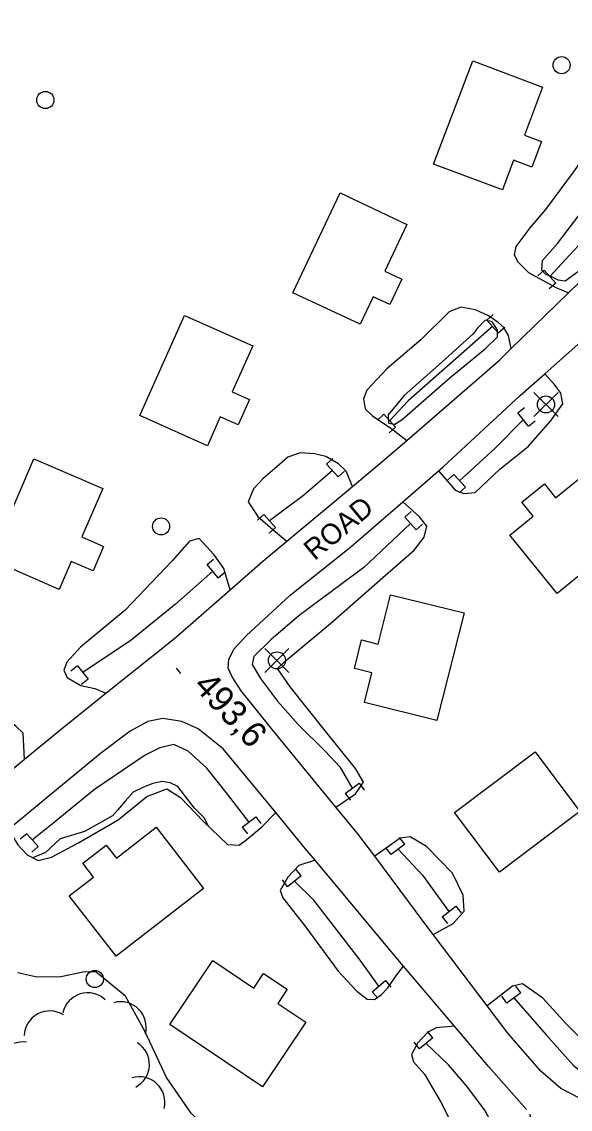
# Model space of a CAD drawing. Extents: x 642515 to 647219, y 6080136 to 6084356.
# Drawn here: x 643716 to 643780.2, y 6081485.1 to 6081612.4 of the extents above; entities that cross this region are included whole.
import ezdxf

# ---------------------------------------------------------------- set-up
doc = ezdxf.new("R2010")
doc.units = 0
for name, color, linetype in [('Level 19', 7, 'Continuous'), ('Level 2', 7, 'Continuous'), ('Level 21', 7, 'Continuous'), ('Level 26', 7, 'Continuous'), ('Level 3', 7, 'Continuous'), ('Level 31', 7, 'Continuous'), ('Level 36', 7, 'Continuous'), ('Level 4', 7, 'Continuous'), ('Level 44', 7, 'Continuous')]:
    doc.layers.add(name, color=color, linetype=linetype)

msp = doc.modelspace()

# ---------------------------------------------------------------- linework, layer by layer
at = {"layer": 'Level 19'}
for points in [[(643799.39, 6081615.12), (643798.24, 6081616.05), (643796.81, 6081616.85), (643795.49, 6081617.32), (643793.8, 6081617.29), (643792.68, 6081616.45), (643791.81, 6081614.33), (643789.04, 6081609.27), (643786.74, 6081604.39), (643783.98, 6081599.77), (643780.67, 6081594.95), (643777.33, 6081590.45), (643775.5, 6081588.27), (643773.83, 6081586.1), (643773.65, 6081585.12), (643774.07, 6081584.3), (643775.32, 6081583.05), (643777.33, 6081581.97), (643778.54, 6081581.29), (643780.02, 6081580.68)], [(643773.31, 6081574.14), (643773, 6081575.69), (643772.46, 6081576.62), (643771.77, 6081577.22), (643770.63, 6081578), (643769.13, 6081578.7), (643767.42, 6081578.99), (643766.05, 6081578.46), (643762.72, 6081575.17), (643758.75, 6081571.76), (643756.41, 6081569.27), (643756, 6081568.27), (643756.19, 6081567.11), (643757.06, 6081566.28), (643759.33, 6081564.74), (643761.09, 6081563.4)], [(643764.79, 6081559.83), (643766.75, 6081557.58), (643767.74, 6081557.17), (643769.07, 6081557.29), (643771.99, 6081560.03), (643775.28, 6081562.67), (643777.9, 6081565.66), (643779.35, 6081567.66), (643779.1, 6081568.93), (643778.39, 6081569.93), (643777.23, 6081571.2)], [(643754.73, 6081558), (643753.96, 6081559.81), (643753.06, 6081560.67), (643751.59, 6081561.5), (643750.28, 6081561.82), (643748.58, 6081561.95), (643747.16, 6081561.45), (643745.87, 6081560.32), (643744.27, 6081558.92), (643743.14, 6081557.72), (643742.51, 6081556.22), (643743.63, 6081554.48), (643745.69, 6081552.68), (643747.02, 6081551.59)], [(643752.77, 6081520.47), (643755.08, 6081522), (643756, 6081523.39), (643755.05, 6081524.98), (643751.4, 6081529.53), (643747.4, 6081534.55), (643745.93, 6081536.67), (643746.81, 6081537.49), (643752.19, 6081542), (643758.28, 6081547.33), (643761.94, 6081550.55), (643763.13, 6081552.08), (643763.41, 6081553.35), (643762.57, 6081554.46), (643760.6, 6081556.19)], [(643740.4, 6081545.91), (643739.63, 6081548.4), (643738.52, 6081549.98), (643736.74, 6081551.91), (643735.63, 6081551.6), (643733.61, 6081549.29), (643728.1, 6081543.52), (643722.87, 6081539.18), (643721.25, 6081537.42), (643720.91, 6081536.51), (643721.29, 6081535.65), (643722.88, 6081534.71), (643724.52, 6081534.33), (643725.84, 6081533.79)], [(643716.3, 6081526.08), (643716.15, 6081529.1), (643715.33, 6081529.89), (643714.31, 6081530.71), (643712.56, 6081530.87), (643709.93, 6081528.64), (643704.45, 6081523.24), (643701.69, 6081519.83), (643701.87, 6081519), (643703.2, 6081517.76), (643704.6, 6081516.72)], [(643714.44, 6081517.83), (643715.53, 6081516.05), (643716.61, 6081514.87), (643717.9, 6081514.19), (643719.45, 6081514.58), (643722.56, 6081516.23), (643727.29, 6081518.97), (643730.61, 6081521.72), (643732.97, 6081522.61), (643734.57, 6081521.58), (643737.21, 6081518.82), (643740.09, 6081516.07), (643741.46, 6081516), (643742.35, 6081516.66), (643744.1, 6081518.15), (643745.73, 6081519.81)], [(643764.18, 6081505.55), (643766.51, 6081506.83), (643767.78, 6081508.28), (643767.66, 6081510.13), (643766.44, 6081512.71), (643763.37, 6081515.85), (643761.49, 6081516.97), (643760.29, 6081516.81), (643757.32, 6081514.7)], [(643750.34, 6081514.23), (643748.44, 6081513.62), (643747.16, 6081512.25), (643746.26, 6081510.7), (643746.56, 6081509.83), (643749.24, 6081506.42), (643753.05, 6081501.27), (643755.22, 6081498.92), (643756.45, 6081497.99), (643757.3, 6081497.93), (643758.1, 6081498.51), (643758.86, 6081499.28), (643759.92, 6081500.84), (643760.68, 6081501.84)], [(643809.2, 6081503.18), (643808.48, 6081506.16), (643807.53, 6081507.83), (643805.66, 6081509.24), (643803.55, 6081509.5), (643801.32, 6081508.42), (643799.27, 6081506.59), (643796.08, 6081502.96), (643788.17, 6081496.5), (643784.22, 6081493.38), (643782.22, 6081492.64), (643779.84, 6081495.02), (643777.02, 6081498.1), (643774.62, 6081499.75), (643773.47, 6081499.48), (643770.5, 6081497.2)], [(643770.52, 6081451.44), (643769.08, 6081448.93), (643768.06, 6081449.67), (643766.12, 6081452.2), (643764.7, 6081454.88), (643763.07, 6081458.11), (643761.71, 6081459.84), (643759.61, 6081461.23), (643754.22, 6081464.21), (643750.58, 6081466.87), (643747.14, 6081470.1), (643742.9, 6081476.39), (643739.67, 6081480.88), (643735.84, 6081484.62), (643732.94, 6081488.82), (643730.41, 6081494.21), (643728.13, 6081498.32), (643724.68, 6081501.12), (643723.31, 6081501.19), (643720.41, 6081500.55), (643717.59, 6081500.6), (643715.5, 6081501.07)], [(643766.65, 6081494.81), (643764.52, 6081494.63), (643763.51, 6081494.08), (643762.38, 6081492.87), (643761.63, 6081491.49), (643761.85, 6081490.62), (643763.15, 6081489.18), (643765.06, 6081485.92), (643767.23, 6081481.67), (643768.34, 6081478.36), (643769.4, 6081476.9), (643770.71, 6081475.98), (643772.26, 6081475.76), (643773.42, 6081476.4), (643774.35, 6081477.55), (643775.71, 6081480.22), (643775.8, 6081482.49), (643775.52, 6081484.52)]]:
    msp.add_lwpolyline(points, dxfattribs=at)
at = {"layer": 'Level 2'}
for points in [[(643781.2, 6081583.17), (643779.63, 6081582.06), (643778.81, 6081582.17), (643777.98, 6081582.6), (643777.36, 6081582.84), (643776.88, 6081583.33), (643776.97, 6081584.46), (643778.72, 6081586.47), (643782.97, 6081592.02)], [(643768.86, 6081575.89), (643764.79, 6081572.19), (643760.78, 6081568.65), (643758.88, 6081566.39), (643758.94, 6081565.42), (643759.67, 6081565.31), (643760.53, 6081565.85), (643766.17, 6081570.75), (643770.27, 6081574.13), (643771.71, 6081575.52), (643771.69, 6081576.36), (643771.07, 6081577.29), (643770.25, 6081577.48), (643769.3, 6081576.49), (643768.86, 6081575.89)], [(643737.9, 6081518.16), (643737.33, 6081519.22), (643736.21, 6081520.35), (643734.27, 6081522.88), (643733.36, 6081523.3), (643732.42, 6081523.44), (643731.32, 6081523.21), (643730.22, 6081522.81), (643729.01, 6081522.21), (643728.08, 6081521.14), (643727.19, 6081520.12), (643726.59, 6081519.44), (643725.08, 6081518.57), (643723.34, 6081517.61), (643720.46, 6081516.74), (643718.77, 6081515.14), (643717.83, 6081514.76), (643717.25, 6081514.54)]]:
    msp.add_lwpolyline(points, dxfattribs=at)
at = {"layer": 'Level 21'}
for points in [[(643710.16, 6081521.04), (643716.3, 6081526.08), (643720.63, 6081529.63), (643725.84, 6081533.79), (643733.91, 6081540.23), (643740.4, 6081545.91), (643744.23, 6081549.26), (643747.02, 6081551.59), (643754.73, 6081558), (643758.17, 6081560.87), (643761.09, 6081563.4), (643771.97, 6081572.84), (643773.31, 6081574.14), (643780.02, 6081580.68), (643781.26, 6081581.89), (643784.65, 6081585.5), (643787.85, 6081590.11), (643792.99, 6081599.62), (643797.87, 6081611.24), (643799.39, 6081615.12)], [(643740.63, 6081535.72), (643740.16, 6081536.74), (643740.22, 6081537.75), (643740.82, 6081538.96), (643742.25, 6081540.5), (643747.42, 6081545.28), (643754.54, 6081550.92), (643760.6, 6081556.19), (643765.33, 6081560.3), (643774.37, 6081568.65), (643777.23, 6081571.2), (643781.14, 6081574.67)], [(643781.4, 6081486.36), (643779.1, 6081487.53), (643776.79, 6081489.56), (643772.91, 6081494.01), (643770.5, 6081497.2), (643764.18, 6081505.55), (643763.2, 6081506.83), (643757.32, 6081514.7), (643755.34, 6081517.35), (643752.77, 6081520.47), (643745.35, 6081529.5), (643741.66, 6081534.09), (643740.63, 6081535.72)], [(643775.08, 6081485.07), (643770.69, 6081490.05), (643766.65, 6081494.81), (643760.68, 6081501.84), (643760.42, 6081502.15), (643750.34, 6081514.23), (643749.18, 6081515.62), (643745.73, 6081519.81), (643739.58, 6081527.28), (643736.65, 6081529.63), (643734.74, 6081530.47), (643732.5, 6081530.84), (643730.75, 6081530.48), (643728.69, 6081529.34), (643725.19, 6081526.73), (643718.97, 6081521.6), (643714.44, 6081517.83)]]:
    msp.add_lwpolyline(points, dxfattribs=at)
at = {"layer": 'Level 26'}
for p, q in [((643777.18, 6081583.34), (643776.42, 6081582.68)), ((643777.18, 6081583.34), (643778.52, 6081581.82)), ((643778.52, 6081581.82), (643777.76, 6081581.16)), ((643770.45, 6081577.49), (643771.19, 6081578.15)), ((643771.79, 6081575.99), (643770.45, 6081577.49)), ((643771.79, 6081575.99), (643772.55, 6081576.65)), ((643758.4, 6081566.46), (643757.66, 6081565.78)), ((643758.4, 6081566.46), (643759.76, 6081564.96)), ((643774.09, 6081566.63), (643774.87, 6081567.25)), ((643775.35, 6081565.05), (643774.09, 6081566.63)), ((643775.35, 6081565.05), (643776.13, 6081565.67)), ((643759.76, 6081564.96), (643759.02, 6081564.3)), ((643751.68, 6081560.63), (643752.42, 6081561.29)), ((643753.02, 6081559.13), (643751.68, 6081560.63)), ((643753.02, 6081559.13), (643753.78, 6081559.79)), ((643766.6, 6081559.42), (643765.84, 6081558.76)), ((643766.6, 6081559.42), (643767.94, 6081557.92)), ((643767.94, 6081557.92), (643767.2, 6081557.26)), ((643760.83, 6081554.42), (643761.57, 6081555.08)), ((643744.35, 6081554.71), (643743.59, 6081554.05)), ((643744.35, 6081554.71), (643745.69, 6081553.21)), ((643762.19, 6081552.92), (643760.83, 6081554.42)), ((643762.19, 6081552.92), (643762.93, 6081553.6)), ((643745.69, 6081553.21), (643744.95, 6081552.55)), ((643737.69, 6081548.86), (643738.45, 6081549.5)), ((643738.99, 6081547.32), (643737.69, 6081548.86)), ((643738.99, 6081547.32), (643739.75, 6081547.96)), ((643722.51, 6081537.01), (643721.73, 6081536.37)), ((643722.51, 6081537.01), (643723.77, 6081535.43)), ((643723.77, 6081535.43), (643722.99, 6081534.81)), ((643753.87, 6081522.06), (643755.49, 6081523.26)), ((643755.49, 6081523.26), (643756.09, 6081522.46)), ((643753.87, 6081522.06), (643754.47, 6081521.26)), ((643741.8, 6081518.1), (643743.38, 6081519.34)), ((643743.38, 6081519.34), (643744, 6081518.56)), ((643741.8, 6081518.1), (643742.4, 6081517.32)), ((643716.56, 6081517.35), (643715.8, 6081516.69)), ((643716.56, 6081517.35), (643717.9, 6081515.85)), ((643760.84, 6081516.14), (643760.24, 6081516.92)), ((643717.9, 6081515.85), (643717.16, 6081515.19)), ((643759.26, 6081514.9), (643758.64, 6081515.68)), ((643760.84, 6081516.14), (643759.26, 6081514.9)), ((643748.7, 6081512.4), (643748.08, 6081513.18)), ((643747.12, 6081511.14), (643746.5, 6081511.94)), ((643748.7, 6081512.4), (643747.12, 6081511.14)), ((643765.22, 6081507.63), (643766.82, 6081508.87)), ((643766.82, 6081508.87), (643767.44, 6081508.09)), ((643765.22, 6081507.63), (643765.84, 6081506.85)), ((643757.04, 6081498.85), (643758.58, 6081500.15)), ((643758.58, 6081500.15), (643759.22, 6081499.39)), ((643757.04, 6081498.85), (643757.68, 6081498.09)), ((643774.42, 6081498.71), (643773.84, 6081499.51)), ((643772.8, 6081497.51), (643772.2, 6081498.31)), ((643774.42, 6081498.71), (643772.8, 6081497.51)), ((643764.14, 6081493.44), (643763.5, 6081494.2)), ((643762.56, 6081492.16), (643761.94, 6081492.94)), ((643764.14, 6081493.44), (643762.56, 6081492.16))]:
    msp.add_line(p, q, dxfattribs=at)
at = {"layer": 'Level 3'}
msp.add_line((643734.05, 6081536.71), (643734.59, 6081536.12), dxfattribs=at)
at = {"layer": 'Level 31'}
for points in [[(643764.22, 6081595.74), (643768.82, 6081607.84), (643776.99, 6081604.74), (643774.86, 6081599.15), (643776.87, 6081598.39), (643775.74, 6081595.4), (643773.59, 6081596.22), (643772.27, 6081592.74), (643764.22, 6081595.74)], [(643747.71, 6081580.68), (643753.26, 6081592.4), (643761.09, 6081588.69), (643758.5, 6081583.22), (643760.51, 6081582.27), (643759.1, 6081579.29), (643757.13, 6081580.22), (643755.61, 6081577.01), (643747.71, 6081580.68)], [(643729.79, 6081566.32), (643735.04, 6081578.03), (643743.05, 6081574.45), (643740.64, 6081569.07), (643742.66, 6081568.17), (643741.33, 6081565.2), (643739.23, 6081566.14), (643737.72, 6081562.78), (643729.79, 6081566.32)], [(643712.32, 6081549.44), (643717.4, 6081561.23), (643725.47, 6081557.75), (643723.03, 6081552.09), (643725.57, 6081550.99), (643724.34, 6081548.13), (643721.78, 6081549.23), (643720.36, 6081545.93), (643712.32, 6081549.44)], [(643788.61, 6081553.54), (643778.7, 6081545.48), (643773.16, 6081552.31), (643775.87, 6081554.51), (643774.54, 6081556.15), (643777.19, 6081558.3), (643778.51, 6081556.68), (643783.16, 6081560.46), (643788.61, 6081553.54)], [(643767.78, 6081543.19), (643764.61, 6081530.59), (643756.11, 6081532.72), (643756.98, 6081536.19), (643754.95, 6081536.7), (643755.78, 6081540.03), (643757.73, 6081539.54), (643759.18, 6081545.33), (643767.78, 6081543.19)], [(643766.68, 6081519.82), (643776.1, 6081526.92), (643781.36, 6081519.94), (643771.95, 6081512.85), (643766.68, 6081519.82)], [(643737.28, 6081510.92), (643727.03, 6081503), (643721.55, 6081510.08), (643724.37, 6081512.27), (643723.12, 6081513.89), (643725.88, 6081516.02), (643727.06, 6081514.5), (643731.73, 6081518.11), (643737.28, 6081510.92)], [(643744.19, 6081487.72), (643733.32, 6081494.99), (643738.34, 6081502.5), (643743.17, 6081499.27), (643744.31, 6081500.98), (643747.08, 6081499.13), (643745.96, 6081497.47), (643749.25, 6081495.27), (643744.19, 6081487.72)]]:
    msp.add_lwpolyline(points, dxfattribs=at)
at = {"layer": 'Level 36'}
for p, q in [((643778.79, 6081566.2), (643775.97, 6081569.02)), ((643775.97, 6081566.2), (643778.79, 6081569.02)), ((643747.28, 6081536.23), (643744.46, 6081539.05)), ((643744.46, 6081536.23), (643747.28, 6081539.05))]:
    msp.add_line(p, q, dxfattribs=at)
for centre in [(643779.21, 6081607.33), (643718.74, 6081603.25), (643777.38, 6081567.61), (643732.3, 6081553.33), (643745.87, 6081537.64), (643724.54, 6081500.33)]:
    msp.add_circle(centre, 1, dxfattribs=at)
at = {"layer": 'Level 4'}
for points in [[(643796.37, 6081616.01), (643793.45, 6081608.18), (643790.34, 6081600.3), (643788.16, 6081595.91), (643785.52, 6081591.94), (643782.72, 6081587.87), (643780.16, 6081585.12), (643777.84, 6081582.58)], [(643771.13, 6081576.73), (643766.82, 6081572.93), (643761.25, 6081568.04), (643759.08, 6081565.72)], [(643774.73, 6081565.83), (643771.4, 6081562.46), (643767.26, 6081558.68)], [(643752.36, 6081559.87), (643748.97, 6081556.94), (643745.01, 6081553.97)], [(643761.51, 6081553.66), (643756.04, 6081548.53), (643748.47, 6081542.91), (643745.15, 6081540.06), (643743.18, 6081538.08), (643742.96, 6081537.14), (643743.96, 6081535.51), (643745.95, 6081532.86), (643748.34, 6081530.15), (643751.54, 6081526.98), (643753.23, 6081525.19), (643754.67, 6081522.66)], [(643738.35, 6081548.08), (643734, 6081544.24), (643728.8, 6081540.02), (643723.13, 6081536.23)], [(643742.58, 6081518.72), (643740.07, 6081521.98), (643737.65, 6081525.01), (643735.46, 6081527), (643733.8, 6081527.78), (643732.17, 6081527.39), (643730.45, 6081526.55), (643724.51, 6081522.52), (643719.57, 6081518.52), (643717.22, 6081516.61)], [(643760.06, 6081515.52), (643762.92, 6081512.48), (643766.02, 6081508.25)], [(643757.8, 6081499.49), (643755.62, 6081502.53), (643750.2, 6081509.55), (643747.92, 6081511.78)], [(643773.62, 6081498.11), (643777.41, 6081493.81), (643780.6, 6081490.19), (643782.89, 6081488.4), (643784.96, 6081487.57), (643786.44, 6081487.79), (643788.2, 6081489.2), (643791.81, 6081492.02), (643798.2, 6081497.17), (643807.83, 6081505.23)], [(643773.87, 6081478.98), (643771.96, 6081481.64), (643770.2, 6081484.99), (643768.08, 6081487.84), (643765.98, 6081490.28), (643763.36, 6081492.8)]]:
    msp.add_lwpolyline(points, dxfattribs=at)
at = {"layer": 'Level 44'}
for centre, start, end in [((643723.71, 6081495.71), 46.9219, 166.8999), ((643727.56, 6081494.67), 345.435, 105.413), ((643719.26, 6081493.59), 57.9186, 177.8966), ((643716.05, 6081489.96), 80.8048, 200.7827), ((643727.93, 6081490.33), 297.7756, 57.7535), ((643729.75, 6081485.89), 346.4483, 106.4263)]:
    msp.add_arc(centre, 3, start, end, dxfattribs=at)

# ---------------------------------------------------------------- texts
at = {"layer": 'Level 21'}
msp.add_text('ROAD', height=2.4, rotation=39.7724, dxfattribs=at).set_placement((643750.27, 6081549.25))
at = {"layer": 'Level 3'}
msp.add_text('493,6', height=3, rotation=312.6129, dxfattribs=at).set_placement((643735.97, 6081534.57))

doc.saveas('drawing.dxf')
